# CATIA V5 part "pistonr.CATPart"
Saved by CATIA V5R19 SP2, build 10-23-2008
Part number: Pistonrob*
Material "Aluminium": density 2710 kg/m3, Young's modulus 7e+10 Pa, Poisson ratio 0.346, thermal expansion 2.36e-05 1/K
Bounding box of the stored display mesh (mm): x -30 to 30, y -29.917 to 29.918, z 1.029 to 50
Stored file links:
  C:\Users\marc\Desktop\boulot\Semestre 3\CFAO\Projet CFAO\robuste\pistonr.CATPart
  C:\Program Files (x86)\Dassault Systemes\B19\intel_a\startup\materials\French\Catalog.CATMaterial
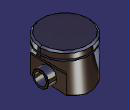
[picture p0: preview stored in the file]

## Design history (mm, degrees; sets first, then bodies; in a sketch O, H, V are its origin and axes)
Parameters
  raypiston = 30 mm
  hautpiston = 50 mm
  epaisseur = 10 mm
  raytrou = 7.5 mm
  rayextrtrou = 10 mm
  hautsegment = 2 mm
Body1 (main body)
  Sketch1 on xy-plane, origin (0, 0, 0), H (1, 0, 0), V (0, 1, 0)
    circle A1 centre (0, 0) radius 30
    radius A1 = 30 {= raypiston}
  Pad1: profile Sketch1, direction (0, 0, 1), length 50 {= hautpiston}
  Chamfer1: length 2, angle 45, on edge [face of Pad1 from Sketch1.A1 | end face of Pad1]
  Body2
    Sketch2 on zx-plane, origin (0, 0, 0), H (-1, 0, 0), V (0, 0, 1)
      line L1 (-20, 0) -> (-20, 27.5)
      point P1 (-20, 0)
      line L2 (-20, 0) -> (-40, 0)
      line L3 (-40, 0) -> (-40, 37.5)
      line L4 (-40, 37.5) -> (-30, 37.5)
      line L5 (-30, 37.5) -> (-20, 27.5)
      distance O P1 = 20 {= 2*raypiston /3}
      length L3 = 37.5 {= 3*hautpiston /4}
      length L2 = 20 {= 2*raypiston /3}
      length L4 = 10 {= raypiston /3}
      angle L5 L4 = 45
      coincidence: P1 H
      vertical: L1 V, L3 V
      horizontal: L2 H, L4 H
    Pad2: profile Sketch2, direction (0, 1, 0), length 40, mirrored extent
    Mirror1: of the body so far, about yz-plane
  Remove1: tool Body2
  Fillet1: radius 5, on edge [face of Pad2 from Sketch2.L1 | face of Pad2 from Sketch2.L5]
  Fillet2: radius 5, on edge [face of Mirror1 | face of Mirror1]
  Shell1: IntOffset 10 {= epaisseur}, Face start face of Pad1, ExtOffset 0
  Body3
    Sketch3 on face of Mirror1, origin (-20, 0, 0), H (0, -1, 0), V (0, 0, 1)
      ellipse A1 centre (0, 0) semi-axes 30, 5 rotation 0
      point P1 (30, 0)
      point P2 (0, 5)
      reference projected line E1 (22.3607, 0) -> (-22.3607, 0) from edge [face of Mirror1 | start face of Pad1]
      "Radius" A1 = 30 {= raypiston}
      distance E1 A1 = 4.1667 {= hautpiston /12}
      coincidence: P1 H, P2 V, A1 P1, A1 P2
      fix: A1
    Pad3: profile Sketch3, direction (1, 0, 0), length 4600
  Remove2: tool Body3
  Sketch4 on face of Mirror1, origin (-20, 0, 0), H (0, -1, 0), V (0, 0, 1)
    circle A1 centre (0, 15) radius 10
    point P1 (0, 15)
    reference projected line E1 (-28, 50) -> (28, 50) from edge [face of Chamfer1 | end face of Pad1]
    radius A1 = 10 {= rayextrtrou}
    distance P1 E1 = 35 {= 0.7*hautpiston}
    radius A1 = 10 (reference)
    coincidence: P1 V
  Pad4: profile Sketch4, direction (-1, 0, 0), length 10 {= epaisseur}
  Mirror2: of Pad4, about yz-plane
  Body4
    Sketch5 on end face of Pad4, origin (-30, 0, 0), H (0, -1, 0), V (0, 0, 1)
      circle A1 centre (0, 15) radius 7.5
      point P1 (0, 15)
      reference projected circle E1 centre (0, 15) radius 10 from edge [face of Pad4 from Sketch4.A1 | end face of Pad4]
      radius A1 = 7.5 {= raytrou}
      coincidence: P1 V
      concentricity: A1 E1
    Pad5: profile Sketch5, direction (1, 0, 0), length 5000
  Remove3: tool Body4
  Chamfer2: length 0.5, angle 45, on edge [face of Pad4 from Sketch4.A1 | end face of Pad4]
  Chamfer3: length 0.5, angle 45, on edge [face of Mirror2 | face of Mirror2]
  Chamfer4: length 1, angle 45, on edge [face of Pad1 from Sketch1.A1 | face of Pad3 from Sketch3.A1]
  Chamfer5: length 1, angle 45, on edge [face of Pad1 from Sketch1.A1 | face of Pad3 from Sketch3.A1]
  Body5
    Sketch6 on zx-plane, origin (0, 0, 0), H (-1, 0, 0), V (0, 0, 1)
      axis line L1 (0, 90) -> (0, -30)
      point P1 (0, 90)
      line L2 (-37, 42) -> (-27, 42)
      line L3 (-27, 42) -> (-27, 40)
      line L4 (-27, 40) -> (-37, 40)
      line L5 (-37, 40) -> (-37, 42)
      point P4 (-27, 42)
      reference projected line E1 (-28, 50) -> (28, 50) from edge [face of Chamfer1 | end face of Pad1]
      distance L3 L1 = 27 {= raypiston -(raypiston /10)}
      length L5 = 2 {= hautsegment}
      distance E1 P4 = 8 {= hautpiston /6.25}
      coincidence: P1 V
      vertical: L1 V, L3 V, L5 V
      horizontal: L2 H, L4 H
    Shaft1: profile Sketch6, axis Sketch6.L1, angle 360
  Remove4: tool Body5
